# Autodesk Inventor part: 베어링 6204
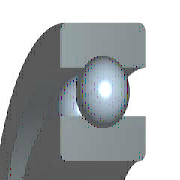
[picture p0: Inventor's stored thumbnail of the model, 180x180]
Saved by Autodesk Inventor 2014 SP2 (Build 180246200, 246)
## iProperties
IsCustomPart: 0
Manager: KYOUNG IL JANG
Company: 한국ATC센터
Created: 2009-02
Part Number: 베어링 6204
Material: Steel, Mild
Description: 깊은 그루브 볼 베어링
Document SubType Name: Modeling
Standard: KS B 2023
Standards Organization: KS
Language: ko-KR
Size Designation: 6204 - 20 x 47 x 14
Categories: <MemberInstance><Categories><Category DisplayName="샤프트 부품" InternalName="7f7aeb1f-a693-4053-b835-cee3144e0d98" Mnemonic="SHFT"><Category DisplayName="베어링" Inter
Density: 1 g/cm^3
Checked By: KYOUNG IL JANG
Vendor: CBT Solutions
Designer: KYOUNG IL JANG
Appearance: _시험-파란색 크롬
Author: KYOUNG IL JANG
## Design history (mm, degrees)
sketch "스케치" dims "d0" = 7.02 (= -0.26 x WD + 0.26 x BD)
  geometry: L1 (3.49, 16.75)-(10.51, 16.75); L2 (7, 16.75)-(7, 13.24); L3 (7, 16.75)-(7, 20.26); L4 (4.392, 14.401)-(0, 14.401); L5 (0, 10)-(14, 10); L6 (4.392, 19.099)-(0, 19.099); L7 (0, 23.5)-(14, 23.5); L8 (14, 10)-(14, 14.401); L9 (9.608, 14.401)-(14, 14.401); L10 (9.608, 19.099)-(14, 19.099); L11 (14, 23.5)-(14, 19.099); L12 (-1.4, 0)-(8.4, 0) reference; L13 (0, -0.3)-(0, 5.3) reference
  constraints: 22 end point, 4 point on line, 2 collinear, 2 perpendicular, 2 symmetric about line, 1 midpoint, 1 parallel, 14 other
  dimensions: "d9" = 20 diameter of L5 L12 (= WD); "d11" = 47 diameter of L7 L12 (= BD); "d12" = 14 distance between parallel lines of L8 L13 (= KB); "d13" = 28.802 diameter of L9 L12 (= 0.326 x BD + 0.674 x WD)
revolve "본체" stored, may be unused: angle "d6" = 90 deg
revolve "볼" stored, may be unused: angle "d7" = 90 deg
pattern_circular "IDS_ARRAYBALL[SIMPL:T]" dims angle "d3" = 360 deg
body "Solid1"
fillet "모깎기1" dims "d1" = 1 (= KRS)
other parameters: "WD" = 20 [user parameter; used in 5 equation terms], "BD" = 47 [user parameter; used in 5 equation terms], "KB" = 14 [user parameter; used in 1 equation term], "KRS" = 1 [user parameter; used in 1 equation term], "d4" = 0, "d5" = 0, "d8" = 0, "d14" = 0, "d15" = 0, "BBA" = 0 [user parameter], "BC0" = 6550000 [user parameter], "BC" = 1.27e+07 [user parameter], "BR" = 23.5 (= 0.5 x BD) [user parameter]
